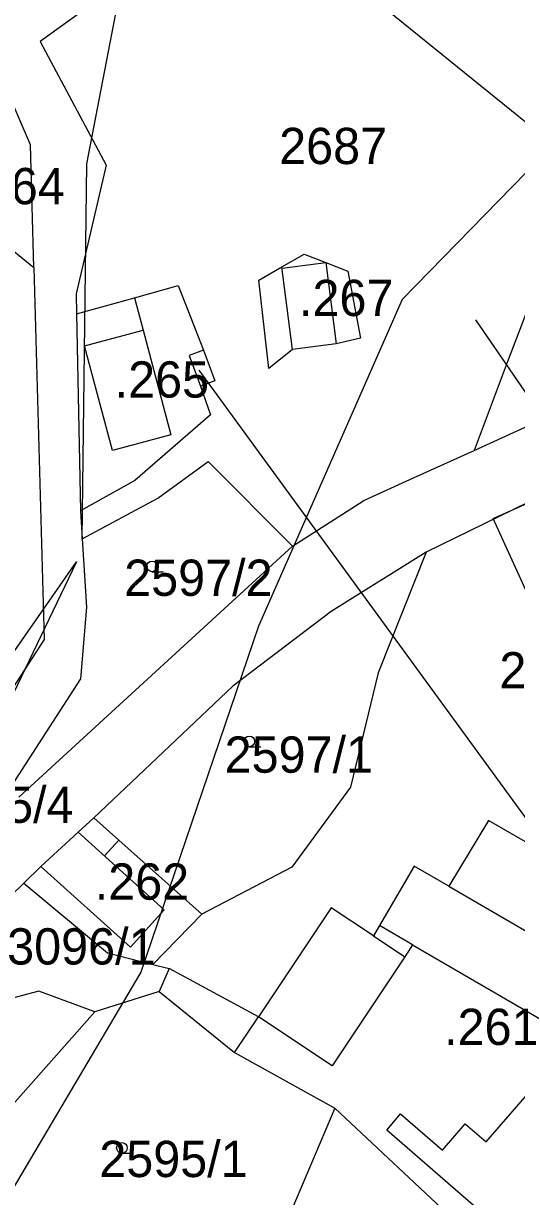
# Model space of a CAD drawing. Extents: x -564810 to -550519, y -1045831 to -1034011.
# Drawn here: x -552496.2 to -552426.8, y -1036404 to -1036239 of the extents above; entities that cross this region are included whole.
import ezdxf

# ---------------------------------------------------------------- set-up
doc = ezdxf.new("R2010")
doc.units = 0
for name, color, linetype in [('KN stav', 7, 'Continuous'), ('Odvodněné plochy', 7, 'Continuous'), ('Parcelní čísla', 7, 'Continuous'), ('STG', 7, 'Continuous'), ('Vedení VN', 7, 'Continuous'), ('Vrstva 22', 7, 'Continuous'), ('Vrstva 33', 7, 'Continuous'), ('Vrstva 4', 7, 'Continuous'), ('zamokř ploch', 7, 'Continuous')]:
    doc.layers.add(name, color=color, linetype=linetype)

msp = doc.modelspace()

# ---------------------------------------------------------------- linework, layer by layer
at = {"layer": 'KN stav'}
for p, q in [((-552466.93, -1036219.2), (-552429.76, -1036249.45)), ((-552486.98, -1036236.6), (-552493.81, -1036241.52)), ((-552495.19, -1036256.09), (-552501.62, -1036241.13)), ((-552493.81, -1036241.52), (-552484.53, -1036258.94)), ((-552429.76, -1036249.45), (-552417.73, -1036259.25)), ((-552494.71, -1036273.32), (-552495.19, -1036256.09)), ((-552484.53, -1036258.94), (-552488.77, -1036277.04)), ((-552417.73, -1036259.25), (-552428.13, -1036286.71)), ((-552499.6, -1036269.37), (-552494.71, -1036273.32)), ((-552459.83, -1036273.25), (-552456.68, -1036271.43)), ((-552456.68, -1036271.43), (-552453.67, -1036272.62)), ((-552453.67, -1036272.62), (-552450.57, -1036273.85)), ((-552494.71, -1036273.32), (-552493.25, -1036325.65)), ((-552463.06, -1036275.12), (-552459.83, -1036273.25)), ((-552450.57, -1036273.85), (-552448.79, -1036283.29)), ((-552480.54, -1036277.58), (-552474.43, -1036275.88)), ((-552474.43, -1036275.88), (-552470.86, -1036284.95)), ((-552461.67, -1036287.54), (-552463.06, -1036275.12)), ((-552488.77, -1036277.04), (-552488.71, -1036279.86)), ((-552488.71, -1036279.86), (-552480.54, -1036277.58)), ((-552488.71, -1036279.86), (-552488.15, -1036307.56)), ((-552452.2, -1036284.05), (-552458.34, -1036284.84)), ((-552448.79, -1036283.29), (-552452.2, -1036284.05)), ((-552470.86, -1036284.95), (-552469.26, -1036289.28)), ((-552458.34, -1036284.84), (-552461.67, -1036287.54)), ((-552428.13, -1036286.71), (-552430.82, -1036293.8)), ((-552469.26, -1036289.28), (-552471.26, -1036290.02)), ((-552427.78, -1036296.78), (-552409.43, -1036288.46)), ((-552471.26, -1036290.02), (-552469.87, -1036294.05)), ((-552469.87, -1036294.05), (-552480.5, -1036303.3)), ((-552430.82, -1036293.8), (-552432.81, -1036299.06)), ((-552432.81, -1036299.06), (-552427.78, -1036296.78)), ((-552441.33, -1036302.92), (-552432.81, -1036299.06)), ((-552477.29, -1036305.76), (-552470.19, -1036300.64)), ((-552470.19, -1036300.64), (-552458.35, -1036312.51)), ((-552480.5, -1036303.3), (-552488.15, -1036307.56)), ((-552446.55, -1036305.29), (-552441.33, -1036302.92)), ((-552418.96, -1036303.28), (-552439.55, -1036313.39)), ((-552487.9, -1036311.48), (-552477.29, -1036305.76)), ((-552448.31, -1036306.09), (-552446.55, -1036305.29)), ((-552488.15, -1036307.56), (-552487.9, -1036311.48)), ((-552458.35, -1036312.51), (-552448.31, -1036306.09)), ((-552496.8, -1036347.86), (-552458.35, -1036312.51)), ((-552487.9, -1036311.48), (-552487.29, -1036321.12)), ((-552439.55, -1036313.39), (-552452.89, -1036321.71)), ((-552439.55, -1036313.39), (-552446.27, -1036330.35)), ((-552487.29, -1036321.12), (-552488.12, -1036331.18)), ((-552452.89, -1036321.71), (-552466.72, -1036332.24)), ((-552493.25, -1036325.65), (-552503.4, -1036341.26)), ((-552446.27, -1036330.35), (-552450.17, -1036346.44)), ((-552488.12, -1036331.18), (-552502.2, -1036352.83)), ((-552466.72, -1036332.24), (-552486.25, -1036350.73)), ((-552450.17, -1036346.44), (-552458.44, -1036357.68)), ((-552486.25, -1036350.73), (-552488.49, -1036352.78)), ((-552482.76, -1036353.88), (-552486.25, -1036350.73)), ((-552430.76, -1036351.11), (-552436.37, -1036360.36)), ((-552421.65, -1036356.42), (-552430.76, -1036351.11)), ((-552488.49, -1036352.78), (-552493.73, -1036357.58)), ((-552471.1, -1036364.31), (-552482.76, -1036353.88)), ((-552493.73, -1036357.58), (-552496.13, -1036359.92)), ((-552458.44, -1036357.68), (-552471.1, -1036364.31)), ((-552441.21, -1036357.54), (-552446.09, -1036365.91)), ((-552436.37, -1036360.36), (-552441.21, -1036357.54)), ((-552510.7, -1036374.1), (-552496.13, -1036359.92)), ((-552496.13, -1036359.92), (-552484.34, -1036369.75)), ((-552452.89, -1036363.39), (-552463.12, -1036378.74)), ((-552446.93, -1036367.36), (-552452.89, -1036363.39)), ((-552477.97, -1036371.37), (-552471.1, -1036364.31)), ((-552446.09, -1036365.91), (-552446.93, -1036367.36)), ((-552484.34, -1036369.75), (-552477.97, -1036371.37)), ((-552477.97, -1036371.37), (-552475.67, -1036371.95)), ((-552475.67, -1036371.95), (-552477.06, -1036375.17)), ((-552463.12, -1036378.74), (-552475.67, -1036371.95)), ((-552494, -1036375.14), (-552506.89, -1036378.57)), ((-552486.12, -1036378.02), (-552494, -1036375.14)), ((-552477.06, -1036375.17), (-552486.12, -1036378.02)), ((-552477.06, -1036375.17), (-552466.48, -1036383.77)), ((-552486.12, -1036378.02), (-552508.46, -1036403.26)), ((-552466.48, -1036383.77), (-552452.36, -1036391.6)), ((-552452.36, -1036391.6), (-552468.4, -1036429.12)), ((-552429.63, -1036412.9), (-552452.36, -1036391.6))]:
    msp.add_line(p, q, dxfattribs=at)
at = {"layer": 'Odvodněné plochy'}
msp.add_lwpolyline([(-552600.32, -1036902.47), (-552513.12, -1036817.19), (-552474.84, -1036779.58), (-552354.8, -1036592.74), (-552400, -1036374.74), (-552430.13, -1036308.64), (-552395.94, -1036293.42), (-552343.81, -1036274.77), (-552167.6, -1036269.39), (-552155.18, -1036416.65), (-552140.47, -1036422.98), (-552086.82, -1036466.24), (-552045.42, -1036498.21), (-551912.44, -1036565.02)], dxfattribs=at)
at = {"layer": 'STG'}
msp.add_lwpolyline([(-552406.18, -1036240.18), (-552442.92, -1036277.85), (-552463.13, -1036323.79), (-552479.67, -1036372.48), (-552509.06, -1036422.1), (-552551.31, -1036504.79), (-552576.11, -1036536.95), (-552634.9, -1036615.96), (-552691.85, -1036672.93), (-552770.85, -1036728.98), (-552832.39, -1036818.1), (-552837.9, -1036875.06), (-552831.47, -1036931.11)], dxfattribs=at)
at = {"layer": 'Vedení VN'}
for points in [[(-552432.62, -1036280.68), (-552381.75, -1036354.88), (-552340.78, -1036472.89), (-552289.91, -1036771.81), (-551953.63, -1037825.94), (-551890.75, -1037944.66), (-551680.22, -1038317.07)], [(-551695.24, -1038326.94), (-551700.71, -1038330.65), (-551972.06, -1037853.73), (-552325.94, -1036770.4), (-552370.45, -1036480.66), (-552411.81, -1036369.59), (-552471.47, -1036287.75)]]:
    msp.add_lwpolyline(points, dxfattribs=at)
at = {"layer": 'Vrstva 33'}
for points in [[(-552487.9, -1036311.48), (-552487.24, -1036258.74), (-552475.61, -1036198.41), (-552465.08, -1036173.84), (-552407.68, -1036141.86), (-552378.62, -1036137.49), (-552358.27, -1036118.6), (-552372.08, -1036090.97), (-552401.14, -1036077.89), (-552462.9, -1036072.08), (-552521.02, -1036078.62), (-552548.63, -1036095.34), (-552579.87, -1036114.96)], [(-552896.64, -1036832.02), (-552870.12, -1036811.16), (-552837.42, -1036779.18), (-552809.09, -1036744.29), (-552783.66, -1036724.66), (-552767.68, -1036700.67), (-552758.23, -1036681.34), (-552737.16, -1036648.63), (-552719, -1036601.38), (-552705.2, -1036538.15), (-552687.76, -1036536.69), (-552655.06, -1036539.6), (-552633.27, -1036541.05), (-552585.32, -1036444.38), (-552563.52, -1036392.48), (-552511.94, -1036348.14), (-552488.69, -1036314.71), (-552549.72, -1036441.91)]]:
    msp.add_lwpolyline(points, dxfattribs=at)
at = {"layer": 'Vrstva 4'}
for p, q in [((-552459.81, -1036273.41), (-552453.67, -1036272.62)), ((-552453.67, -1036272.62), (-552452.2, -1036284.05)), ((-552458.34, -1036284.84), (-552459.83, -1036273.25)), ((-552480.54, -1036277.58), (-552479.33, -1036282.15)), ((-552487.57, -1036284.34), (-552479.33, -1036282.15)), ((-552479.33, -1036282.15), (-552475.42, -1036296.89)), ((-552483.66, -1036299.07), (-552487.57, -1036284.34)), ((-552470.86, -1036284.95), (-552472.86, -1036285.69)), ((-552472.86, -1036285.69), (-552471.26, -1036290.02)), ((-552475.42, -1036296.89), (-552483.66, -1036299.07)), ((-552476.39, -1036363.7), (-552488.49, -1036352.77)), ((-552484.79, -1036356.11), (-552482.76, -1036353.88)), ((-552493.73, -1036357.58), (-552481.13, -1036368.96)), ((-552436.37, -1036360.36), (-552418.12, -1036371)), ((-552481.13, -1036368.96), (-552476.39, -1036363.7)), ((-552441.45, -1036368.62), (-552446.09, -1036365.91)), ((-552446.94, -1036367.35), (-552442.55, -1036370.28)), ((-552441.45, -1036368.62), (-552442.55, -1036370.28)), ((-552441.45, -1036368.62), (-552423, -1036379.37)), ((-552442.55, -1036370.28), (-552452.78, -1036385.62)), ((-552466.48, -1036383.77), (-552463.12, -1036378.74)), ((-552452.78, -1036385.62), (-552463.12, -1036378.74)), ((-552431.1, -1036396.33), (-552424.01, -1036388.15)), ((-552445.09, -1036394.66), (-552443.13, -1036392.4)), ((-552443.13, -1036392.4), (-552437.25, -1036397.5)), ((-552427.24, -1036410.15), (-552445.09, -1036394.66)), ((-552437.25, -1036397.5), (-552434.04, -1036393.79)), ((-552434.04, -1036393.79), (-552431.1, -1036396.33))]:
    msp.add_line(p, q, dxfattribs=at)
at = {"layer": 'zamokř ploch'}
for p, q in [((-552478.06, -1036316.12), (-552476.46, -1036316.12)), ((-552464.41, -1036340.74), (-552462.81, -1036340.74)), ((-552482.31, -1036397.93), (-552480.71, -1036397.93))]:
    msp.add_line(p, q, dxfattribs=at)
for centre in [(-552478.06, -1036315.37), (-552464.41, -1036339.99), (-552482.31, -1036397.18)]:
    msp.add_circle(centre, 0.75, dxfattribs=at)

# ---------------------------------------------------------------- texts
at = {"layer": 'Parcelní čísla'}
for s, p in [('2687', (-552460.21, -1036258.78)), ('2597/2', (-552482, -1036319.52)), ('2600/1', (-552429.25, -1036332.54)), ('2597/1', (-552467.88, -1036344.4)), ('3125/4', (-552509.98, -1036351.45)), ('3096/1', (-552498.45, -1036371.38)), ('2595/1', (-552485.5, -1036401.28))]:
    msp.add_text(s, height=5.1, dxfattribs=at).set_placement(p)
at = {"layer": 'Vrstva 22'}
for s, p in [('.264', (-552503.63, -1036264.43)), ('.267', (-552457.42, -1036280.16)), ('.265', (-552483.34, -1036291.63)), ('.262', (-552486.14, -1036362.26)), ('.261', (-552437.02, -1036382.7))]:
    msp.add_text(s, height=5.1, dxfattribs=at).set_placement(p)

doc.saveas('drawing.dxf')
